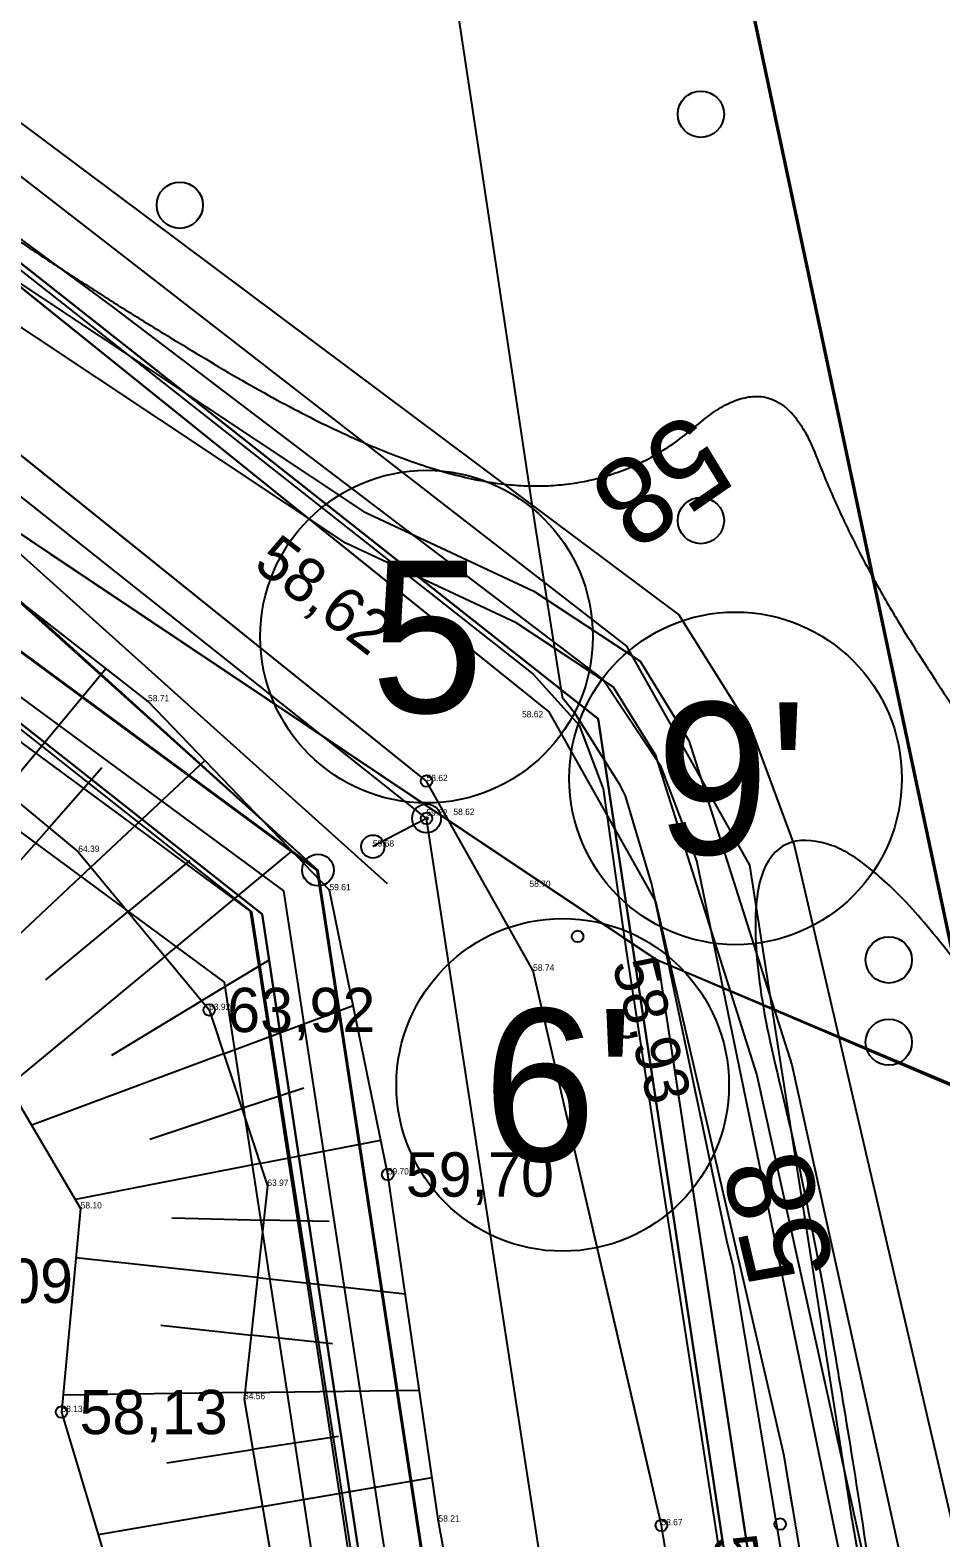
# Model space of a CAD drawing. Extents: x 700746 to 706058, y 6570320 to 6580460.
# Drawn here: x 703261.4 to 703311.8, y 6577035.9 to 6577119.3 of the extents above; entities that cross this region are included whole.
import ezdxf

# ---------------------------------------------------------------- set-up
doc = ezdxf.new("R2010")
doc.units = 0
for name, color, linetype in [('HALJASTUS', 7, 'Continuous'), ('HORISONTAAL-EH2000', 7, 'Continuous'), ('illumineerimisjooned', 7, 'Continuous'), ('Kaitsevöönd', 7, 'Continuous'), ('kataster', 7, 'Continuous'), ('KORGUS-EH2000', 7, 'Continuous'), ('KPOHULIIN', 7, 'Continuous'), ('maeeraldised_kehtivad', 7, 'Continuous'), ('MOOTKORG-EH2000', 7, 'Continuous'), ('mäeeraldise teenindusmaa', 7, 'Continuous'), ('PIIR', 7, 'Continuous'), ('Plokid', 7, 'Continuous'), ('POST', 7, 'Continuous'), ('RELJEEF', 7, 'Continuous'), ('TEE', 7, 'Continuous'), ('Tmaad_maeeraldised_kehtivad', 7, 'Continuous'), ('VTRASS', 7, 'Continuous'), ('VWX2_MV_PLOKK', 7, 'Continuous')]:
    doc.layers.add(name, color=color, linetype=linetype)

msp = doc.modelspace()

# ---------------------------------------------------------------- linework, layer by layer
at = {"layer": 'HALJASTUS'}
for centre in [(703298.551, 6577114.636), (703298.551, 6577114.636), (703269.717, 6577109.604), (703269.717, 6577109.604), (703298.551, 6577092.159), (703298.551, 6577092.159), (703308.945, 6577067.854), (703308.945, 6577063.307)]:
    msp.add_circle(centre, 1.28, dxfattribs=at)
at = {"layer": 'HORISONTAAL-EH2000'}
msp.add_open_spline([(703324.635, 6577221.481), (703319.132, 6577215.75), (703312.66, 6577207.755), (703318.256, 6577196.393), (703318.056, 6577187.239), (703313.365, 6577179.54), (703300.634, 6577171.987), (703287.337, 6577167.011), (703275.77, 6577167.382), (703274.241, 6577160.297), (703275.814, 6577157.458), (703270.144, 6577153.424), (703258.565, 6577155.53), (703243.73, 6577148.162), (703229.37, 6577144.115), (703228.21, 6577139.53), (703242.661, 6577120.372), (703262.742, 6577106.047), (703282.024, 6577094.689), (703293.912, 6577093.595), (703302.774, 6577101.292), (703307.021, 6577090.304), (703314.056, 6577079.423), (703319.234, 6577071.759), (703318.718, 6577059.952), (703306.431, 6577075.844), (703299.968, 6577072.577), (703306.272, 6577047.613), (703310.574, 6577014.715)], degree=2, dxfattribs=at)
at = {"layer": 'illumineerimisjooned'}
for points in [[(703281.213, 6577072.058), (703170.159, 6577171.774), (703168.929, 6577173.195), (703127.168, 6577443.561), (702857.567, 6577467.93), (702860.381, 6577440.007), (702861.165, 6577378.171)], [(702976.891, 6576643.26), (702915.328, 6577059.558), (702785.772, 6577104.455), (702748.407, 6577249.47), (702721.642, 6577298.043), (702716.252, 6577332.033), (702861.102, 6577284.56), (703066.328, 6577217.365), (703088.858, 6577210.018), (703169.031, 6577150.466), (703230.271, 6577104.95), (703275.453, 6577071.675), (703358.033, 6576531.935)], [(703290.041, 6576963.147), (703188.508, 6577001.438), (703016.934, 6577112.515), (702852.033, 6577230.395), (702862.776, 6577281.723), (703065.707, 6577215.464), (703087.928, 6577208.218), (703167.838, 6577148.861), (703229.081, 6577103.342), (703273.601, 6577070.555), (703290.041, 6576963.147)]]:
    msp.add_lwpolyline(points, dxfattribs=at)
at = {"layer": 'Kaitsevöönd'}
for points in [[(703127.193, 6577494.83), (703185.616, 6577495.492), (703196.043, 6577489.865), (703207.628, 6577483.079), (703220.041, 6577477.287), (703228.316, 6577473.48), (703231.792, 6577472.156), (703232.454, 6577468.681), (703247.183, 6577370.537), (703286.242, 6577112.681), (703289.387, 6577091.828), (703290.877, 6577082.394), (703291.539, 6577081.567), (703294.021, 6577077.595), (703294.352, 6577076.933), (703295.842, 6577071.967), (703299.979, 6577052.272), (703300.31, 6577050.948), (703311.399, 6576985.078)], [(703166.121, 6577263.7), (703175.702, 6577194.955), (703182.367, 6577173.968), (703184.335, 6577171.888), (703234.777, 6577133.694), (703297.335, 6577086.947), (703301.39, 6577080.476), (703303.707, 6577074.198), (703312.832, 6577035.002)], [(703165.354, 6577251.752), (703169.343, 6577224.655), (703172.908, 6577198.638), (703175.621, 6577184.862), (703178.313, 6577176.367), (703181.162, 6577170.26), (703188.358, 6577162.238), (703201.92, 6577151.175), (703218.707, 6577139), (703227.774, 6577131.827), (703239.94, 6577120.915), (703259.404, 6577106.258), (703279.889, 6577092.665), (703289.304, 6577088.256), (703295.187, 6577084.374), (703297.887, 6577080.001), (703303.575, 6577062.05), (703310.1, 6577032.568)], [(703306.33, 6577034.518), (703298.332, 6577073.332), (703296.36, 6577078.547), (703293.106, 6577083.404), (703266.019, 6577103.99), (703229.003, 6577131.254), (703192.483, 6577158.96), (703180.016, 6577168.453), (703176.926, 6577173.475), (703171.465, 6577190.198), (703170.693, 6577193.123), (703165.341, 6577231.26)], [(703308.131, 6577032.212), (703301.642, 6577061.531), (703296.055, 6577079.161), (703293.717, 6577082.948), (703288.324, 6577086.506), (703278.907, 6577090.917), (703258.248, 6577104.625), (703238.668, 6577119.369), (703226.484, 6577130.297), (703217.499, 6577137.405), (703200.7, 6577149.59), (703186.973, 6577160.787), (703179.475, 6577169.146), (703176.446, 6577175.639), (703173.68, 6577184.365), (703170.935, 6577198.309), (703167.363, 6577224.373)], [(703332.065, 6576694.743), (703304.442, 6576872.638), (703273.694, 6577070.52), (703230.233, 6577104.832), (703217.52, 6577108.973), (703142.719, 6577173.75), (703139.166, 6577177.33), (703138.297, 6577181.096), (703138.49, 6577185.153), (703140.421, 6577188.437), (703144.379, 6577190.851), (703147.661, 6577191.817), (703151.812, 6577191.141), (703154.805, 6577189.403), (703166.583, 6577179.261), (703228.658, 6577126.14), (703241.595, 6577121.215), (703289.275, 6577083.661), (703291.813, 6577080.846), (703293.137, 6577077.314), (703294.406, 6577068.373), (703355.652, 6576672.76)], [(703154.91, 6577189.152), (703230.532, 6577125.647), (703239.404, 6577123.376), (703292.869, 6577081.186), (703317.705, 6576917.046)], [(703317.705, 6576917.046), (703292.869, 6577081.186), (703239.404, 6577123.376), (703230.532, 6577125.647), (703154.91, 6577189.152)], [(703297.93, 6576914.054), (703274.276, 6577070.381), (703230.34, 6577105.051), (703221.159, 6577107.401), (703142.048, 6577173.836)], [(703142.048, 6577173.836), (703221.159, 6577107.401), (703230.34, 6577105.051), (703274.276, 6577070.381), (703297.93, 6576914.054)]]:
    msp.add_lwpolyline(points, dxfattribs=at)
at = {"layer": 'kataster'}
for points in [[(703360.09, 6576531.99), (703277.36, 6577072.83), (703167.04, 6577172.32), (703125.43, 6577441.71), (702859.8, 6577465.72), (702862.38, 6577440.12), (702863.2, 6577375.41), (702851.4, 6577379.23), (702839.86, 6577381.59), (702831.19, 6577380.43), (702820.1, 6577376.69), (702754.28, 6577347.92), (702741.83, 6577344.92), (702732.67, 6577344.2), (702712.5, 6577346.91), (702704.73, 6577347.96), (702701.8, 6577345.85), (702700.78, 6577341.43), (702712.4, 6577226.51), (702651.69, 6577159.42), (702595.69, 6577121.68), (702628.71, 6576895.25), (702720.42, 6576547.28)], [(702754.28, 6577347.92), (702820.1, 6577376.69), (702831.19, 6577380.43), (702839.86, 6577381.59), (702851.4, 6577379.23), (702863.2, 6577375.41), (702878.06, 6577370.59), (702900.72, 6577367.74), (702944.77, 6577367.92), (702961.68, 6577364.05), (703005.04, 6577344.66), (703019.19, 6577342.06), (703041.25, 6577339.7), (703057.1, 6577329.85), (703096.08, 6577280.59), (703119.31, 6577233.95), (703129.16, 6577218.59), (703141.54, 6577201.64), (703167.04, 6577172.32), (703168.73, 6577170.37), (703277.36, 6577072.83), (703231.53, 6577106.55), (703089.87, 6577211.79), (702713.81, 6577334.91)]]:
    msp.add_lwpolyline(points, dxfattribs=at)
msp.add_lwpolyline([(702852.27, 6575508.89), (702837.26, 6575620.73), (702848.38, 6575976.59), (702782.85, 6576063.35), (702782.57, 6576096.37), (702842.53, 6576210.56), (702853.4, 6576267.5), (702844.46, 6576489.93), (702877.29, 6576548.25), (702974.72, 6576643.9), (702913.57, 6577058.07), (702784.04, 6577102.84), (702746.48, 6577248.7), (702719.69, 6577297.36), (702713.81, 6577334.91), (703089.87, 6577211.79), (703231.53, 6577106.55), (703277.36, 6577072.83), (703360.09, 6576531.99), (703311.6, 6576228.52), (703293.62, 6575965.66), (703298.84, 6575573.29)], close=True, dxfattribs=at)
at = {"layer": 'KORGUS-EH2000'}
for centre in [(703283.369, 6577077.748), (703283.369, 6577075.688), (703291.727, 6577069.156), (703271.34, 6577065.09), (703281.22, 6577055.99), (703263.17, 6577042.85), (703296.365, 6577036.581), (703302.937, 6577036.651)]:
    msp.add_circle(centre, 0.32, dxfattribs=at)
at = {"layer": 'KPOHULIIN'}
msp.add_lwpolyline([(703296.185, 6576992.32), (703283.369, 6577075.688), (703236.355, 6577112.959), (703223.684, 6577117.354), (703148.385, 6577181.716)], dxfattribs=at)
at = {"layer": 'maeeraldised_kehtivad'}
msp.add_lwpolyline([(702849.808, 6577229.527), (702861.724, 6577286.461), (703066.949, 6577219.266), (703089.789, 6577211.819), (703170.224, 6577152.072), (703231.46, 6577106.558), (703277.305, 6577072.795), (703294.683, 6576959.259), (703187.602, 6576999.642), (703015.809, 6577110.861)], close=True, dxfattribs=at)
at = {"layer": 'mäeeraldise teenindusmaa'}
msp.add_lwpolyline([(702859.8, 6577465.72), (703125.43, 6577441.71), (703167.04, 6577172.32), (703168.73, 6577170.37), (703277.36, 6577072.83), (703231.53, 6577106.55), (703089.87, 6577211.79), (702713.81, 6577334.91), (702712.5, 6577346.91), (702732.67, 6577344.2), (702741.83, 6577344.92), (702754.28, 6577347.92), (702820.1, 6577376.69), (702831.19, 6577380.43), (702839.86, 6577381.59), (702851.4, 6577379.23), (702863.2, 6577375.41), (702862.38, 6577440.12), (702859.8, 6577465.72)], dxfattribs=at)
at = {"layer": 'PIIR'}
for centre, radius in [((703283.369, 6577085.74), 9.2), ((703300.467, 6577077.901), 9.2), ((703277.36, 6577072.83), 0.88), ((703277.36, 6577072.83), 0.88), ((703277.36, 6577072.83), 0.88), ((703290.901, 6577060.945), 9.2)]:
    msp.add_circle(centre, radius, dxfattribs=at)
at = {"layer": 'Plokid'}
msp.add_line((703296.172, 6577067.83), (703382.069, 6576503.627), dxfattribs=at)
msp.add_lwpolyline([(703124.556, 6577445.959), (703074.894, 6577705.02), (703364.857, 6577738.287), (703222.854, 6577490.693), (703314.212, 6577060.217), (703296.172, 6577067.83), (703262.59, 6577090.291)], dxfattribs=at)
msp.add_lwpolyline([(703287.547, 6576966.226), (703189.415, 6577003.234), (703018.06, 6577114.169), (702854.258, 6577231.263), (702863.9, 6577277.331), (703064.465, 6577211.662), (703086.067, 6577204.618), (703165.453, 6577145.65), (703226.702, 6577100.127), (703272.178, 6577066.636)], close=True, dxfattribs=at)
at = {"layer": 'POST'}
msp.add_line((703283.369, 6577075.688), (703280.399, 6577074.127), dxfattribs=at)
msp.add_line((703283.369, 6577075.688), (703280.399, 6577074.127), dxfattribs=at)
msp.add_line((703283.369, 6577075.688), (703280.399, 6577074.127), dxfattribs=at)
for centre, radius in [((703283.369, 6577075.688), 0.8), ((703283.369, 6577075.688), 0.8), ((703283.369, 6577075.688), 0.8), ((703283.369, 6577075.688), 0.0747), ((703283.369, 6577075.688), 0.0747), ((703283.369, 6577075.688), 0.0747), ((703280.399, 6577074.127), 0.64), ((703280.399, 6577074.127), 0.64), ((703280.399, 6577074.127), 0.64)]:
    msp.add_circle(centre, radius, dxfattribs=at)
at = {"layer": 'RELJEEF'}
for p, q in [((703260.02, 6577077.212), (703265.628, 6577083.978)), ((703264.802, 6577072.983), (703271.102, 6577078.889)), ((703265.406, 6577078.474), (703262.483, 6577075.17)), ((703258.393, 6577070.546), (703262.483, 6577075.17)), ((703268.885, 6577068.054), (703275.916, 6577073.879)), ((703264.802, 6577072.983), (703255.864, 6577064.604)), ((703270.268, 6577073.356), (703266.843, 6577070.518)), ((703262.305, 6577066.759), (703266.843, 6577070.518)), ((703268.885, 6577068.054), (703260.236, 6577060.89)), ((703274.632, 6577067.826), (703270.926, 6577065.59)), ((703265.962, 6577062.593), (703270.926, 6577065.59)), ((703272.141, 6577062.668), (703279.305, 6577065.339)), ((703272.141, 6577062.668), (703261.521, 6577058.708)), ((703276.578, 6577060.766), (703273.147, 6577059.63)), ((703268.055, 6577057.945), (703273.147, 6577059.63)), ((703274.152, 6577056.592), (703280.831, 6577057.89)), ((703274.152, 6577056.592), (703263.937, 6577054.607)), ((703269.272, 6577053.583), (703274.353, 6577053.469)), ((703277.983, 6577053.388), (703274.353, 6577053.469)), ((703274.006, 6577050.288), (703263.973, 6577051.385)), ((703274.006, 6577050.288), (703282.185, 6577049.394)), ((703268.666, 6577047.653), (703273.658, 6577047.107)), ((703278.161, 6577046.615), (703273.658, 6577047.107)), ((703273.31, 6577043.926), (703263.258, 6577043.781)), ((703273.31, 6577043.926), (703282.965, 6577044.066)), ((703278.49, 6577041.503), (703273.748, 6577040.769)), ((703268.991, 6577040.032), (703273.748, 6577040.769)), ((703274.288, 6577037.615), (703283.674, 6577039.222)), ((703274.288, 6577037.615), (703265.204, 6577036.06))]:
    msp.add_line(p, q, dxfattribs=at)
for points in [[(703164.02, 6577157.81), (703171.03, 6577151.9), (703175.77, 6577147.5), (703180.96, 6577142.99), (703185.59, 6577140.44), (703189.33, 6577137.39), (703192.75, 6577134.35), (703195.36, 6577130.71), (703198.35, 6577127.24), (703202.17, 6577123.23), (703205.99, 6577120.14), (703210.33, 6577117.03), (703215.78, 6577111.72), (703219.63, 6577109), (703222.57, 6577107.24), (703226.8, 6577104.03), (703233, 6577100.19), (703244.58, 6577090.62), (703253.05, 6577082.99), (703264.1, 6577073.83), (703271.34, 6577065.09), (703274.56, 6577055.36), (703273.27, 6577043.56), (703276.36, 6577025.51)], [(703166.49, 6577150.21), (703170.5, 6577146.78), (703174.34, 6577144.69), (703176.86, 6577142.26), (703178.72, 6577140.34), (703181.29, 6577137.31), (703184.64, 6577135.32), (703187.88, 6577131.82), (703190.25, 6577126.46), (703194.43, 6577120.55), (703198.73, 6577116.52), (703204.34, 6577112.43), (703211.17, 6577107.88), (703218.98, 6577102.83), (703223.36, 6577100.46), (703232.96, 6577090.99), (703243.22, 6577081.21), (703246.95, 6577076.11), (703253.33, 6577066.74), (703260.2, 6577060.95), (703264.23, 6577054.11), (703263.17, 6577042.85), (703266.27, 6577032.5)], [(703289.96, 6577004.49), (703284.03, 6577036.79), (703281.22, 6577055.99), (703278, 6577071.71), (703267.96, 6577082.16), (703252.11, 6577094.52), (703240.96, 6577102.25), (703223.97, 6577114.69), (703215.12, 6577123.5)]]:
    msp.add_lwpolyline(points, dxfattribs=at)
at = {"layer": 'TEE'}
for points in [[(703303.627, 6577037.582), (703303.154, 6577040.421), (703296.055, 6577071.096), (703290.159, 6577081.588), (703186.337, 6577164.979)], [(703352.188, 6576141.743), (703333.891, 6576240.908), (703343.285, 6576290.998), (703349.944, 6576325.798), (703355.472, 6576356.506), (703364.509, 6576409.388), (703371.49, 6576445.789), (703377.052, 6576478.468), (703380.318, 6576501.696), (703378.705, 6576535.395), (703372.605, 6576579.277), (703366.542, 6576617.948), (703359.597, 6576660.205), (703326.861, 6576887.215), (703316.48, 6576960.36), (703310.761, 6576994.71), (703303.154, 6577040.421), (703296.055, 6577071.096), (703290.159, 6577081.588), (703186.337, 6577164.979)], [(703295.809, 6577038.984), (703289.266, 6577067.256), (703283.369, 6577077.748), (703179.547, 6577161.139)], [(703345.398, 6576137.903), (703327.102, 6576237.068), (703336.562, 6576290.115), (703343.247, 6576326.507), (703348.807, 6576358.127), (703358.182, 6576409.796), (703364.654, 6576448.177), (703369.91, 6576476.489), (703373.714, 6576502.518), (703371.54, 6576534.249), (703365.816, 6576575.437), (703359.752, 6576614.108), (703352.807, 6576656.365), (703320.071, 6576883.375), (703309.691, 6576956.52), (703303.971, 6576990.87), (703296.365, 6577036.581), (703289.266, 6577067.256), (703283.369, 6577077.748), (703179.547, 6577161.139)]]:
    msp.add_lwpolyline(points, dxfattribs=at)
at = {"layer": 'Tmaad_maeeraldised_kehtivad'}
msp.add_lwpolyline([(702974.764, 6576643.974), (702913.527, 6577058.065), (702784.103, 6577102.917), (702746.534, 6577248.726), (702719.722, 6577297.384), (702713.764, 6577334.953), (702861.724, 6577286.461), (703066.949, 6577219.266), (703089.789, 6577211.819), (703089.789, 6577211.819), (703170.224, 6577152.072), (703231.46, 6577106.558), (703277.305, 6577072.795), (703360.057, 6576531.928)], dxfattribs=at)
at = {"layer": 'VTRASS'}
msp.add_lwpolyline([(703187.298, 6577168.252), (703294.432, 6577085.209), (703301.236, 6577073.103), (703306.844, 6577037.233), (703313.095, 6577001.738), (703318.333, 6576962.356), (703331.426, 6576870.746), (703362.089, 6576663.779), (703368.34, 6576626.426), (703375.774, 6576583.156), (703383.803, 6576538.658), (703383.922, 6576537.608)], dxfattribs=at)
at = {"layer": 'VWX2_MV_PLOKK'}
for points in [[(703222.9, 6577490.69), (703314.13, 6577060.15), (703296.09, 6577067.87), (703170.22, 6577152.1), (703125.37, 6577441.7), (703121.85, 6577464.43), (703121.06, 6577464.52), (703074.97, 6577705.03), (703364.79, 6577738.24)], [(703044.07, 6577449.05), (703125.37, 6577441.7), (703167.08, 6577172.26), (703170.22, 6577152.1), (703231.53, 6577106.55), (703277.36, 6577072.83), (703360.09, 6576531.99), (703311.6, 6576228.52), (703293.62, 6575965.66), (703294.04, 6575933.77), (703295.43, 6575829.7), (703298.36, 6575609.6), (703298.84, 6575573.29), (703155.29, 6575552.59), (703145.59, 6575981.92), (703123.04, 6576234.88), (703120.61, 6576749.6), (703011.59, 6576989.47), (703015.74, 6577110.88), (702996.73, 6577210.32)], [(702849.88, 6577229.56), (702861.72, 6577286.46), (703066.96, 6577219.29), (703089.79, 6577211.82), (703170.22, 6577152.07), (703231.53, 6577106.55), (703277.36, 6577072.83), (703294.74, 6576959.21), (703187.67, 6576999.67), (703015.74, 6577110.88)], [(702849.88, 6577229.56), (702861.72, 6577286.46), (703066.96, 6577219.29), (703089.79, 6577211.82), (703170.22, 6577152.07), (703231.53, 6577106.55), (703277.36, 6577072.83), (703294.74, 6576959.21), (703187.67, 6576999.67), (703015.74, 6577110.88)], [(703170.54, 6577151.86), (703296.17, 6577067.83), (703382.07, 6576503.63), (703324.97, 6576203.4), (703311.73, 6576015.89), (703294.04, 6575933.77), (703293.62, 6575965.66), (703311.6, 6576228.52), (703360.09, 6576531.99), (703277.36, 6577072.83), (703231.53, 6577106.55)]]:
    msp.add_lwpolyline(points, close=True, dxfattribs=at)

# ---------------------------------------------------------------- texts
at = {"layer": 'HORISONTAAL-EH2000'}
for rotation, p in [(214.63315, (703297.953, 6577098.323)), (103.36974, (703306.001, 6577050.643))]:
    msp.add_text('58', height=4.8, rotation=rotation, dxfattribs=at).set_placement(p)
at = {"layer": 'KORGUS-EH2000'}
for s, rotation, p in [('58,62 ', 322.58308, (703273.712, 6577089.582)), ('58,93 ', 284.57709, (703293.623, 6577067.653)), ('58,67 ', 279.35468, (703299.173, 6577035.863))]:
    msp.add_text(s, height=2.45, rotation=rotation, dxfattribs=at).set_placement(p)
for s, p in [('63,92', (703272.34, 6577063.865)), ('59,70', (703282.22, 6577054.765)), ('59,09', (703255.61, 6577048.885)), ('58,13', (703264.17, 6577041.625))]:
    msp.add_text(s, height=2.45, dxfattribs=at).set_placement(p)
at = {"layer": 'MOOTKORG-EH2000'}
for s, p in [('58.71', (703267.96, 6577082.16)), ('58.62', (703288.65, 6577081.275)), ('58.62', (703283.369, 6577077.748)), ('59.22', (703283.365, 6577075.833)), ('58.62', (703284.853, 6577075.879)), ('64.39', (703264.1, 6577073.83)), ('59.68', (703280.399, 6577074.127)), ('58.70', (703289.062, 6577071.895)), ('59.61', (703278, 6577071.71)), ('58.74', (703289.266, 6577067.256)), ('63.92', (703271.34, 6577065.09)), ('59.70', (703281.22, 6577055.99)), ('63.97', (703274.56, 6577055.36)), ('58.10', (703264.23, 6577054.11)), ('64.56', (703273.27, 6577043.56)), ('58.13', (703263.17, 6577042.85)), ('58.21', (703284.03, 6577036.79)), ('58.67', (703296.365, 6577036.581))]:
    msp.add_text(s, height=0.35, dxfattribs=at).set_placement(p)
at = {"layer": 'PIIR'}
for s, p in [('5', (703280.283, 6577081.54)), ("9'", (703296.065, 6577073.701)), ("6'", (703286.499, 6577056.745))]:
    msp.add_text(s, height=8.4, dxfattribs=at).set_placement(p)

doc.saveas('drawing.dxf')
